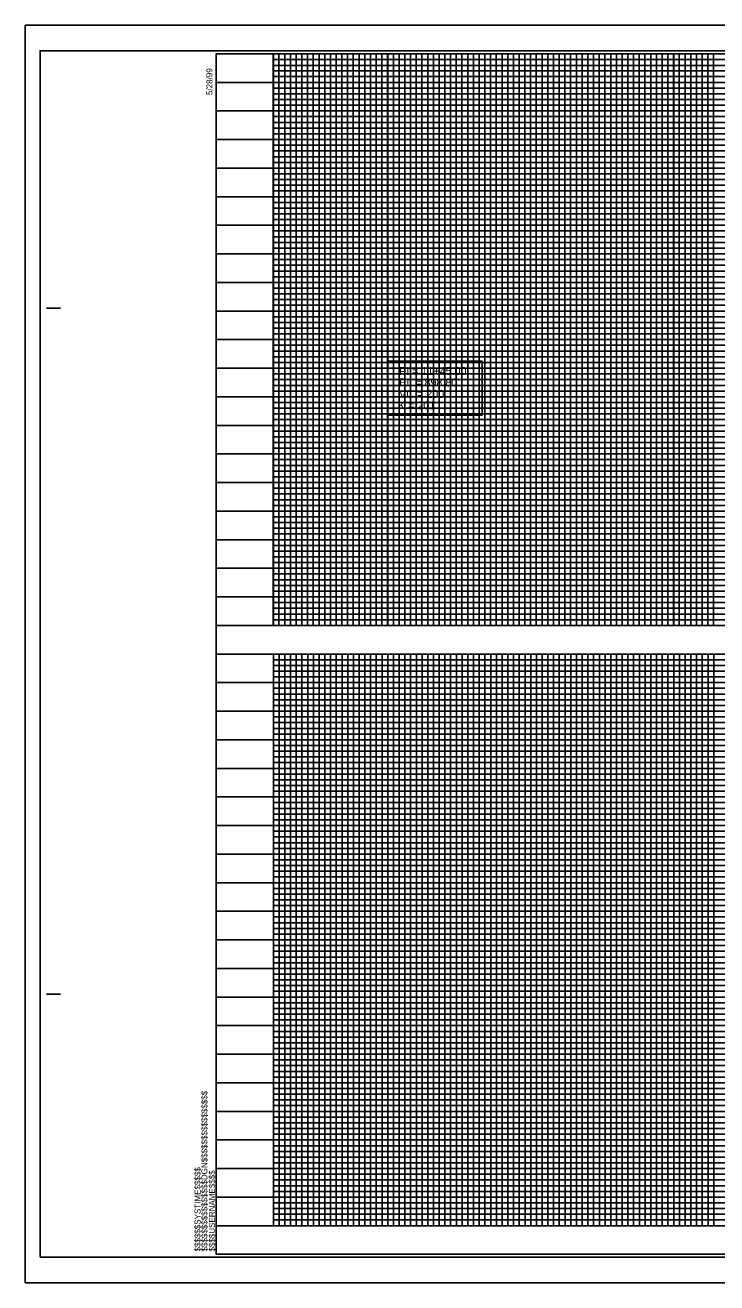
# Model space of a CAD drawing. Extents: x 1648862 to 1650715, y 820691 to 821791.
# Drawn here: x 1648862 to 1649467, y 820691 to 821791 of the extents above; entities that cross this region are included whole.
import ezdxf

# ---------------------------------------------------------------- set-up
doc = ezdxf.new("R2010")
doc.units = 0
for name, color, linetype in [('Prop Grid Mask', 7, 'Continuous'), ('Prop Vertical Profile Curve Label', 7, 'Continuous'), ('Prop VPI Label', 7, 'Continuous'), ('Sheet Cutting Line CELL', 7, 'Continuous'), ('Sheet DOT Grid CELL', 7, 'Continuous'), ('Sheet Layout Profile Border Port 1', 7, 'Continuous'), ('Sheet Layout Profile Border Port 2', 7, 'Continuous'), ('Sheet Plot Border Inside CELL', 7, 'Continuous'), ('Sheet Plot Border Outside CELL', 7, 'Continuous'), ('Sheet Profile CELL', 7, 'Continuous'), ('Sheet Profile Grid Major CELL', 7, 'Continuous'), ('Sheet Profile Grid Middle CELL', 7, 'Continuous'), ('Sheet Profile Grid Minor CELL', 7, 'Continuous')]:
    doc.layers.add(name, color=color, linetype=linetype)

msp = doc.modelspace()

# ---------------------------------------------------------------- linework, layer by layer
at = {"layer": 'Prop Grid Mask'}
msp.add_lwpolyline([(1649179.3, 821497), (1649179.3, 821450), (1649261.9, 821450), (1649261.9, 821497)], close=True, dxfattribs=at)
at = {"layer": 'Sheet Cutting Line CELL'}
for p, q in [((1650546.3, 821791), (1648862.3, 821791)), ((1648862.3, 821791), (1648862.3, 820691)), ((1648862.3, 820691), (1650546.3, 820691))]:
    msp.add_line(p, q, dxfattribs=at)
at = {"layer": 'Sheet DOT Grid CELL'}
for p, q in [((1649079.3, 821266), (1649079.3, 821766)), ((1649129.3, 821266), (1649129.3, 821766)), ((1649179.3, 821266), (1649179.3, 821766)), ((1649229.3, 821266), (1649229.3, 821766)), ((1649279.3, 821266), (1649279.3, 821766)), ((1649329.3, 821266), (1649329.3, 821766)), ((1649379.3, 821266), (1649379.3, 821766)), ((1649429.3, 821266), (1649429.3, 821766)), ((1650329.2, 821716), (1649029.3, 821716)), ((1650329.2, 821666), (1649029.3, 821666)), ((1650329.3, 821616), (1649029.3, 821616)), ((1650529.3, 821566), (1649029.3, 821566)), ((1650529.3, 821516), (1649029.3, 821516)), ((1650529.3, 821466), (1649029.3, 821466)), ((1650529.3, 821416), (1649029.3, 821416)), ((1650529.3, 821366), (1649029.3, 821366)), ((1650529.3, 821316), (1649029.3, 821316)), ((1649029.3, 821241), (1650529.2, 821241)), ((1649079.3, 821241), (1649079.3, 820741)), ((1649129.3, 821241), (1649129.3, 820741)), ((1649179.3, 821241), (1649179.3, 820741)), ((1649229.3, 821241), (1649229.3, 820741)), ((1649279.3, 821241), (1649279.3, 820741)), ((1649329.3, 821241), (1649329.3, 820741)), ((1649379.3, 821241), (1649379.3, 820741)), ((1649429.3, 821241), (1649429.3, 820741)), ((1649029.3, 821191), (1650529.2, 821191)), ((1649029.3, 821141), (1650529.2, 821141)), ((1649029.3, 821091), (1650529.2, 821091)), ((1649029.3, 821041), (1650529.2, 821041)), ((1649029.3, 820991), (1650529.2, 820991)), ((1649029.3, 820941), (1650529.2, 820941)), ((1649029.3, 820891), (1650529.2, 820891)), ((1649029.3, 820841), (1650529.2, 820841)), ((1649029.3, 820791), (1650529.2, 820791))]:
    msp.add_line(p, q, dxfattribs=at)
at = {"layer": 'Sheet Layout Profile Border Port 1'}
msp.add_lwpolyline([(1649079.3, 821605), (1649079.3, 821266), (1650479.3, 821266), (1650479.3, 821605)], dxfattribs=at)
at = {"layer": 'Sheet Layout Profile Border Port 2'}
msp.add_lwpolyline([(1649079.3, 821241), (1650479.3, 821241), (1650479.3, 820741), (1649079.3, 820741)], close=True, dxfattribs=at)
at = {"layer": 'Sheet Plot Border Inside CELL'}
msp.add_lwpolyline([(1648875.3, 820713.5), (1650541.8, 820713.5), (1650541.8, 821768.6), (1648875.3, 821768.6)], close=True, dxfattribs=at)
at = {"layer": 'Sheet Plot Border Outside CELL'}
msp.add_lwpolyline([(1648862.3, 820691), (1650546.3, 820691), (1650546.3, 821791), (1648862.3, 821791)], close=True, dxfattribs=at)
at = {"layer": 'Sheet Profile CELL'}
for p, q in [((1648880.8, 821543.5), (1648893.3, 821543.5)), ((1649029.3, 821266), (1650529.3, 821266)), ((1649029.3, 821241), (1650529.3, 821241)), ((1648880.8, 820943.5), (1648893.3, 820943.5)), ((1650529.3, 820741), (1649029.3, 820741)), ((1649029.3, 820716), (1650529.3, 820716)), ((1649029.3, 820716), (1649029.3, 820716)), ((1649029.3, 820716), (1649029.3, 820716)), ((1649029.3, 820716), (1649029.3, 820716)), ((1649029.3, 820716), (1649029.3, 820716)), ((1649029.3, 820716), (1649029.3, 820716)), ((1649029.3, 820716), (1649029.3, 820716)), ((1649029.3, 820716), (1649029.3, 820716))]:
    msp.add_line(p, q, dxfattribs=at)
msp.add_lwpolyline([(1650529.3, 821766), (1649029.3, 821766), (1649029.3, 820716), (1650529.3, 820716)], close=True, dxfattribs=at)
msp.add_lwpolyline([(1649066.8, 820716), (1649066.8, 820716)], dxfattribs=at)
at = {"layer": 'Sheet Profile Grid Major CELL'}
msp.add_line((1649029.3, 820741), (1649029.3, 820741), dxfattribs=at)
for points in [[(1649079.2, 821766), (1649079.2, 821266), (1649129.2, 821266), (1649129.2, 821766), (1649179.2, 821766), (1649179.2, 821266), (1649229.2, 821266), (1649229.2, 821766), (1649279.2, 821766), (1649279.2, 821266), (1649329.2, 821266), (1649329.2, 821766), (1649379.2, 821766), (1649379.2, 821266), (1649429.2, 821266), (1649429.2, 821766), (1649479.2, 821766)], [(1649029.2, 821716), (1650329.2, 821716)], [(1650329.2, 821666), (1649029.2, 821666), (1649029.2, 821616), (1650329.2, 821616)], [(1650529.2, 821566), (1649029.2, 821566), (1649029.2, 821516), (1650529.2, 821516)], [(1650529.2, 821466), (1649029.2, 821466), (1649029.2, 821416), (1650529.2, 821416)], [(1650529.2, 821366), (1649029.2, 821366), (1649029.2, 821366), (1649029.2, 821316), (1650529.2, 821316)], [(1649079.3, 821241), (1649079.3, 820741), (1649129.3, 820741), (1649129.3, 821241), (1649179.3, 821241), (1649179.3, 820741), (1649229.3, 820741), (1649229.3, 821241), (1649279.3, 821241), (1649279.3, 820741), (1649329.3, 820741), (1649329.3, 821241), (1649379.3, 821241), (1649379.3, 820741), (1649429.3, 820741), (1649429.3, 821241), (1649479.3, 821241)], [(1650529.3, 821191), (1649029.3, 821191)], [(1650529.3, 821141), (1649029.3, 821141), (1649029.3, 821091), (1650529.3, 821091)], [(1650529.3, 821041), (1649029.3, 821041), (1649029.3, 820991), (1650529.3, 820991)], [(1650529.3, 820941), (1649029.3, 820941), (1649029.3, 820891), (1650529.3, 820891)], [(1650529.3, 820841), (1649029.3, 820841), (1649029.3, 820841), (1649029.3, 820791), (1650529.3, 820791)], [(1650529.3, 820741), (1649029.3, 820741)]]:
    msp.add_lwpolyline(points, dxfattribs=at)
at = {"layer": 'Sheet Profile Grid Middle CELL'}
msp.add_line((1649029.2, 821741), (1650179.2, 821741), dxfattribs=at)
for points in [[(1649104.2, 821766), (1649104.2, 821266), (1649154.2, 821266), (1649154.2, 821766), (1649204.2, 821766), (1649204.2, 821266), (1649254.2, 821266), (1649254.2, 821766), (1649304.2, 821766), (1649304.2, 821266), (1649354.2, 821266), (1649354.2, 821766), (1649404.2, 821766), (1649404.2, 821266), (1649454.2, 821266), (1649454.2, 821766), (1649504.2, 821766)], [(1650329.2, 821691), (1649029.2, 821691), (1649029.2, 821641), (1650329.2, 821641)], [(1650529.2, 821591), (1649029.2, 821591), (1649029.2, 821541), (1650354.2, 821541)], [(1650529.2, 821491), (1649029.2, 821491), (1649029.2, 821441), (1650529.2, 821441)], [(1650529.2, 821391), (1649029.2, 821391), (1649029.2, 821341), (1650529.2, 821341)], [(1650529.2, 821291), (1649029.2, 821291)], [(1649054.3, 821241), (1649104.3, 821241), (1649104.3, 820741), (1649154.3, 820741), (1649154.3, 821241), (1649204.3, 821241), (1649204.3, 820741), (1649254.3, 820741), (1649254.3, 821241), (1649304.3, 821241), (1649304.3, 820741), (1649354.3, 820741), (1649354.3, 821241), (1649404.3, 821241), (1649404.3, 820741), (1649454.3, 820741), (1649454.3, 821241), (1649504.3, 821241)], [(1649029.3, 821216), (1650529.3, 821216)], [(1650529.3, 821166), (1649029.3, 821166), (1649029.3, 821116), (1650529.3, 821116)], [(1650529.3, 821066), (1649029.3, 821066), (1649029.3, 821016), (1650529.3, 821016)], [(1650529.3, 820966), (1649029.3, 820966), (1649029.3, 820916), (1650529.3, 820916)], [(1650529.3, 820866), (1649029.3, 820866), (1649029.3, 820816), (1650529.3, 820816)], [(1650529.3, 820766), (1649029.3, 820766)]]:
    msp.add_lwpolyline(points, dxfattribs=at)
at = {"layer": 'Sheet Profile Grid Minor CELL'}
for p, q in [((1649079.2, 821761), (1650179.2, 821761)), ((1649079.2, 821756), (1649079.2, 821756)), ((1649079.2, 821756), (1649079.2, 821756)), ((1649079.2, 821756), (1649079.2, 821756)), ((1650179.2, 821756), (1649079.2, 821755.7)), ((1649079.3, 821761), (1650037.4, 821761)), ((1649079.3, 821756), (1649079.3, 821756)), ((1649079.2, 821751), (1650179.2, 821751)), ((1649079.4, 821655.9), (1649079.4, 821651)), ((1650329.2, 821631), (1649079.2, 821631)), ((1650329.2, 821626), (1649079.2, 821626)), ((1650329.2, 821621), (1649079.2, 821621)), ((1649079.2, 821611), (1650329.2, 821611)), ((1650329.2, 821606), (1649079.2, 821606)), ((1649079.2, 821601), (1650479.2, 821601)), ((1650479.2, 821581), (1649079.2, 821581)), ((1649079.2, 821576), (1650479.2, 821576)), ((1650479.2, 821556), (1649079.2, 821556)), ((1649079.2, 821551), (1650479.2, 821551)), ((1650479.2, 821531), (1649079.2, 821531)), ((1649079.2, 821526), (1650479.2, 821526)), ((1650479.2, 821521), (1649079.2, 821521)), ((1649079.2, 821511), (1650479.2, 821511)), ((1650479.2, 821506), (1649079.2, 821506)), ((1649079.2, 821501), (1650479.2, 821501)), ((1650479.2, 821496), (1649079.2, 821496)), ((1649079.2, 821486), (1650479.2, 821486)), ((1650479.2, 821481), (1649079.2, 821481)), ((1649079.2, 821476), (1650479.2, 821476)), ((1650479.2, 821471), (1649079.2, 821471)), ((1649079.2, 821461), (1650479.2, 821461)), ((1650479.2, 821456), (1649079.2, 821456)), ((1649079.2, 821451), (1650479.2, 821451)), ((1650479.2, 821446), (1649079.2, 821446)), ((1649079.2, 821436), (1650479.2, 821436)), ((1650479.2, 821431), (1649079.2, 821431)), ((1649079.2, 821426), (1650479.2, 821426)), ((1650479.2, 821421), (1649079.2, 821421)), ((1649079.2, 821411), (1650479.2, 821411)), ((1650479.2, 821406), (1649079.2, 821406)), ((1649079.2, 821401), (1650479.2, 821401)), ((1650479.2, 821396), (1649079.2, 821396)), ((1649079.2, 821386), (1650479.2, 821386)), ((1650479.2, 821381), (1649079.2, 821381)), ((1650479.2, 821376), (1649079.2, 821376)), ((1650479.2, 821371), (1649079.2, 821371)), ((1649079.2, 821361), (1650479.2, 821361)), ((1650479.2, 821356), (1649079.2, 821356)), ((1649079.2, 821351), (1650479.2, 821351)), ((1650479.2, 821346), (1649079.2, 821346)), ((1649079.2, 821336), (1650479.2, 821336)), ((1650479.2, 821331), (1649079.2, 821331)), ((1649079.2, 821326), (1650479.2, 821326)), ((1650479.2, 821321), (1649079.2, 821321)), ((1649079.2, 821311), (1650479.2, 821311)), ((1650479.2, 821306), (1649079.2, 821306)), ((1649079.2, 821301), (1650479.2, 821301)), ((1650479.2, 821296), (1649079.2, 821296)), ((1649079.2, 821286), (1650479.2, 821286)), ((1650479.2, 821281), (1649079.2, 821281)), ((1649079.2, 821276), (1650479.2, 821276)), ((1649079.3, 821236), (1650479.3, 821236)), ((1650479.3, 821231), (1649079.3, 821231)), ((1649079.3, 821226), (1650479.3, 821226)), ((1650479.3, 821221), (1649079.3, 821221)), ((1649079.3, 821211), (1650479.3, 821211)), ((1650479.3, 821206), (1649079.3, 821206)), ((1649079.3, 821201), (1650479.3, 821201)), ((1650479.3, 821196), (1649079.3, 821196)), ((1649079.3, 821186), (1650479.3, 821186)), ((1650479.3, 821181), (1649079.3, 821181)), ((1649079.3, 821176), (1650479.3, 821176)), ((1650479.3, 821171), (1649079.3, 821171)), ((1649079.3, 821161), (1650479.3, 821161)), ((1650479.3, 821156), (1649079.3, 821156)), ((1649079.3, 821151), (1650479.3, 821151)), ((1650479.3, 821146), (1649079.3, 821146)), ((1649079.3, 821136), (1650479.3, 821136)), ((1650479.3, 821131), (1649079.3, 821131)), ((1649079.3, 821126), (1650479.3, 821126)), ((1650479.3, 821121), (1649079.3, 821121)), ((1649079.3, 821111), (1650479.3, 821111)), ((1650479.3, 821106), (1649079.3, 821106)), ((1649079.3, 821101), (1650479.3, 821101)), ((1650479.3, 821096), (1649079.3, 821096)), ((1649079.3, 821086), (1650479.3, 821086)), ((1650479.3, 821081), (1649079.3, 821081)), ((1649079.3, 821076), (1650479.3, 821076)), ((1650479.3, 821071), (1649079.3, 821071)), ((1649079.3, 821061), (1650479.3, 821061)), ((1650479.3, 821056), (1649079.3, 821056)), ((1649079.3, 821051), (1650479.3, 821051)), ((1650479.3, 821046), (1649079.3, 821046.2)), ((1649079.3, 821036), (1650479.3, 821036)), ((1650479.3, 821031), (1649079.3, 821031)), ((1649079.3, 821026), (1650479.3, 821026)), ((1650479.3, 821021), (1649079.3, 821021)), ((1649079.3, 821011), (1650479.3, 821011)), ((1650479.3, 821006), (1649079.3, 821006)), ((1649079.3, 821001), (1650479.3, 821001)), ((1650479.3, 820996), (1649079.3, 820996)), ((1649079.3, 820986), (1650479.3, 820986)), ((1650479.3, 820981), (1649079.3, 820981)), ((1649079.3, 820976), (1650479.3, 820976)), ((1650479.3, 820971), (1649079.3, 820971)), ((1649079.3, 820961), (1650479.3, 820961)), ((1650479.3, 820956), (1649079.3, 820956)), ((1649079.3, 820951), (1650479.3, 820951)), ((1650479.3, 820946), (1649079.3, 820946)), ((1649079.3, 820936), (1650479.3, 820936)), ((1650479.3, 820931), (1649079.3, 820931)), ((1649079.3, 820926), (1650479.3, 820926)), ((1650479.3, 820921), (1649079.3, 820921)), ((1649079.3, 820911), (1650479.3, 820911)), ((1650479.3, 820906), (1649079.3, 820906)), ((1649079.3, 820901), (1650479.3, 820901)), ((1650479.3, 820896), (1649079.3, 820896)), ((1649079.3, 820886), (1650479.3, 820886)), ((1650479.3, 820881), (1649079.3, 820881)), ((1649079.3, 820876), (1650479.3, 820876)), ((1650479.3, 820871), (1649079.3, 820871)), ((1649079.3, 820861), (1650479.3, 820861)), ((1650479.3, 820856), (1649079.3, 820856)), ((1649079.3, 820851), (1650479.3, 820851)), ((1650479.3, 820846), (1649079.3, 820846)), ((1649079.3, 820836), (1650479.3, 820836)), ((1650479.3, 820831), (1649079.3, 820831)), ((1649079.3, 820826), (1650479.3, 820826)), ((1650479.3, 820821), (1649079.3, 820821)), ((1649079.3, 820811), (1650479.3, 820811)), ((1650479.3, 820806), (1649079.3, 820806)), ((1649079.3, 820801), (1650479.3, 820801)), ((1650479.3, 820796), (1649079.3, 820796)), ((1649079.3, 820786), (1650479.3, 820786)), ((1650479.3, 820781), (1649079.3, 820781)), ((1649079.3, 820776), (1650479.3, 820776)), ((1650479.3, 820771), (1649079.3, 820771)), ((1649079.3, 820761), (1650479.3, 820761)), ((1650479.3, 820756), (1649079.3, 820756)), ((1649079.3, 820751), (1650479.3, 820751)), ((1649079.3, 820746), (1650479.3, 820746))]:
    msp.add_line(p, q, dxfattribs=at)
for points in [[(1649084.2, 821766), (1649084.2, 821266), (1649089.2, 821266), (1649089.2, 821766), (1649094.2, 821766), (1649094.2, 821266), (1649099.2, 821266), (1649099.2, 821766), (1649109.2, 821766), (1649109.2, 821266), (1649114.2, 821266), (1649114.2, 821766), (1649119.2, 821766), (1649119.2, 821266), (1649124.2, 821266), (1649134.2, 821266), (1649139.2, 821266), (1649139.2, 821766), (1649144.2, 821766), (1649144.2, 821266), (1649149.2, 821266), (1649149.2, 821766), (1649159.2, 821766), (1649159.2, 821266), (1649164.2, 821266), (1649164.2, 821766), (1649169.2, 821766), (1649169.2, 821266), (1649174.2, 821266), (1649174.2, 821766), (1649184.2, 821766), (1649184.2, 821266), (1649189.2, 821266), (1649189.2, 821766), (1649194.2, 821766), (1649194.2, 821266), (1649199.2, 821266), (1649199.2, 821766), (1649209.2, 821766), (1649209.2, 821266), (1649214.2, 821266), (1649214.2, 821766), (1649219.2, 821766), (1649219.2, 821266), (1649224.2, 821266), (1649224.2, 821766), (1649234.2, 821766), (1649234.2, 821266), (1649239.2, 821266), (1649239.2, 821766), (1649244.2, 821766), (1649244.2, 821266), (1649249.2, 821266), (1649249.2, 821766), (1649259.2, 821766), (1649259.2, 821266), (1649264.2, 821266), (1649264.2, 821766), (1649269.2, 821766), (1649269.2, 821266), (1649274.2, 821266), (1649274.2, 821766), (1649284.2, 821766), (1649284.2, 821266), (1649289.2, 821266), (1649289.2, 821766), (1649294.2, 821766), (1649294.2, 821266)], [(1649124.2, 821266), (1649124.2, 821766), (1649134.2, 821766), (1649134.2, 821266)], [(1649294.2, 821266), (1649299.2, 821266), (1649299.2, 821766), (1649309.2, 821766), (1649309.2, 821266), (1649314.2, 821266), (1649314.2, 821766), (1649319.2, 821766), (1649319.2, 821266), (1649324.2, 821266), (1649324.2, 821766), (1649334.2, 821766), (1649334.2, 821266), (1649339.2, 821266), (1649339.2, 821766), (1649344.2, 821766), (1649344.2, 821266), (1649349.2, 821266), (1649349.2, 821766), (1649359.2, 821766), (1649359.2, 821266), (1649364.2, 821266), (1649364.2, 821766), (1649369.2, 821766), (1649369.2, 821266), (1649374.2, 821266), (1649374.2, 821766), (1649384.2, 821766), (1649384.2, 821266), (1649389.2, 821266), (1649389.2, 821766), (1649394.2, 821766), (1649394.2, 821266), (1649399.2, 821266), (1649399.2, 821766), (1649409.2, 821766), (1649409.2, 821266), (1649414.2, 821266), (1649414.2, 821766), (1649419.2, 821766), (1649419.2, 821266), (1649424.2, 821266), (1649424.2, 821766), (1649434.2, 821766), (1649434.2, 821266), (1649439.2, 821266), (1649439.2, 821766), (1649444.2, 821766), (1649444.2, 821266), (1649449.2, 821266), (1649449.2, 821766), (1649459.2, 821766), (1649459.2, 821266), (1649464.2, 821266), (1649464.2, 821766), (1649469.2, 821766)], [(1650179.2, 821746), (1649079.2, 821746), (1649079.2, 821736), (1650329.2, 821736)], [(1650329.2, 821731), (1649079.2, 821731), (1649079.2, 821726), (1650329.2, 821726)], [(1650329.2, 821721), (1649079.2, 821721), (1649079.2, 821711), (1650329.2, 821711)], [(1650329.2, 821706), (1649079.2, 821706), (1649079.2, 821701), (1650329.2, 821701)], [(1650329.2, 821696), (1649079.2, 821696), (1649079.2, 821686), (1650329.2, 821686)], [(1650329.2, 821681), (1649079.2, 821681), (1649079.2, 821676), (1650329.2, 821676)], [(1650329.2, 821671), (1649079.2, 821671), (1649079.2, 821661), (1650329.2, 821661)], [(1650329.2, 821646), (1649079.2, 821646), (1649079.2, 821636), (1650329.2, 821636)], [(1650329.2, 821655.9), (1649079.3, 821655.9), (1649079.3, 821651), (1650329.2, 821651)], [(1650479.2, 821596), (1649079.2, 821596), (1649079.2, 821586), (1650479.2, 821586)], [(1650479.2, 821571), (1649079.2, 821571), (1649079.2, 821561), (1650479.2, 821561)], [(1650479.2, 821546), (1649079.2, 821546), (1649079.2, 821536), (1650479.2, 821536)], [(1650479.2, 821271), (1649079.2, 821271)], [(1649079.3, 821241), (1649084.3, 821241), (1649084.3, 820741), (1649089.3, 820741), (1649089.3, 821241), (1649094.3, 821241), (1649094.3, 820741), (1649099.3, 820741), (1649099.3, 821241), (1649109.3, 821241), (1649109.3, 820741), (1649114.3, 820741), (1649114.3, 821241), (1649119.3, 821241), (1649119.3, 820741), (1649124.3, 820741), (1649134.3, 820741), (1649139.3, 820741), (1649139.3, 821241), (1649144.3, 821241), (1649144.3, 820741), (1649149.3, 820741), (1649149.3, 821241), (1649159.3, 821241), (1649159.3, 820741), (1649164.3, 820741), (1649164.3, 821241), (1649169.3, 821241), (1649169.3, 820741), (1649174.3, 820741), (1649174.3, 821241), (1649184.3, 821241), (1649184.3, 820741), (1649189.3, 820741), (1649189.3, 821241), (1649194.3, 821241), (1649194.3, 820741), (1649199.3, 820741), (1649199.3, 821241), (1649209.3, 821241), (1649209.3, 820741), (1649214.3, 820741), (1649214.3, 821241), (1649219.3, 821241), (1649219.3, 820741), (1649224.3, 820741), (1649224.3, 821241), (1649234.3, 821241), (1649234.3, 820741), (1649239.3, 820741), (1649239.3, 821241), (1649244.3, 821241), (1649244.3, 820741), (1649249.3, 820741), (1649249.3, 821241), (1649259.3, 821241), (1649259.3, 820741), (1649264.3, 820741), (1649264.3, 821241), (1649269.3, 821241), (1649269.3, 820741), (1649274.3, 820741), (1649274.3, 821241), (1649284.3, 821241), (1649284.3, 820741), (1649289.3, 820741), (1649289.3, 821241), (1649294.3, 821241), (1649294.3, 820741)], [(1649124.3, 820741), (1649124.3, 821241), (1649134.3, 821241), (1649134.3, 820741)], [(1649294.3, 820741), (1649299.3, 820741), (1649299.3, 821241), (1649309.3, 821241), (1649309.3, 820741), (1649314.3, 820741), (1649314.3, 821241), (1649319.3, 821241), (1649319.3, 820741), (1649324.3, 820741), (1649324.3, 821241), (1649334.3, 821241), (1649334.3, 820741), (1649339.3, 820741), (1649339.3, 821241), (1649344.3, 821241), (1649344.3, 820741), (1649349.3, 820741), (1649349.3, 821241), (1649359.3, 821241), (1649359.3, 820741), (1649364.3, 820741), (1649364.3, 821241), (1649369.3, 821241), (1649369.3, 820741), (1649374.3, 820741), (1649374.3, 821241), (1649384.3, 821241), (1649384.3, 820741), (1649389.3, 820741), (1649389.3, 821241), (1649394.3, 821241), (1649394.3, 820741), (1649399.3, 820741), (1649399.3, 821241), (1649409.3, 821241), (1649409.3, 820741), (1649414.3, 820741), (1649414.3, 821241), (1649419.3, 821241), (1649419.3, 820741), (1649424.3, 820741), (1649424.3, 821241), (1649434.3, 821241), (1649434.3, 820741), (1649439.3, 820741), (1649439.3, 821241), (1649444.3, 821241), (1649444.3, 820741), (1649449.3, 820741), (1649449.3, 821241), (1649459.3, 821241), (1649459.3, 820741), (1649464.3, 820741), (1649464.3, 821241), (1649469.3, 821241)]]:
    msp.add_lwpolyline(points, dxfattribs=at)

# ---------------------------------------------------------------- texts
at = {"layer": 'Prop Vertical Profile Curve Label'}
for s, p in [("VC = 200'", (1649189.3, 821465)), ('K = 201', (1649188.3, 821455))]:
    msp.add_text(s, height=7, dxfattribs=at).set_placement(p)
at = {"layer": 'Prop VPI Label'}
for s, p in [('PI = 11+45.00', (1649189.3, 821485)), ("EL = 898.80'", (1649189.3, 821475))]:
    msp.add_text(s, height=7, dxfattribs=at).set_placement(p)
at = {"layer": 'Sheet Profile CELL'}
for s, p in [('5/28/99', (1649026, 821729.9)), ('$$$$$$$$$$$$$$$$DGN$$$$$$$$$$$$$$$$', (1649021.6, 820718.4)), ('$$$$$$SYSTIME$$$$$', (1649015.6, 820718.4)), ('$$$$USERNAME$$$$', (1649028.2, 820718.4))]:
    msp.add_text(s, height=5.25, rotation=90, dxfattribs=at).set_placement(p)

doc.saveas('drawing.dxf')
